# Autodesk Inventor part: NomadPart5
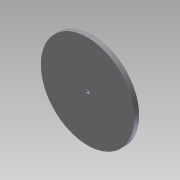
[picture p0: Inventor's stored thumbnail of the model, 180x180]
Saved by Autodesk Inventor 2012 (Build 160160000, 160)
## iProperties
Created: 2012-10
Part Number: NomadPart5
Material: Default
Document SubType Name: Modeling
Designer: TechShop Member
Density: 1 g/cm^3
Author: TechShop Member
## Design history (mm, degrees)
sketch "Sketch1"
  geometry: C1 r 61.139 at (0, 0); 1 further point
  constraints: 1 centre point, 1 coincident
  dimensions: "d0" = 122.27814 diameter of C1
extrude "Extrusion1" new body sketch "Sketch1" distance "d1" = 6.35; taper "d2" = 0 deg
sketch "Sketch2"
  geometry: C1 r 61.139 at (0, 0) reference; 1 further point
  constraints: 1 coincident
hole "Hole1" sketch "Sketch2" at (0, 0) diameter "d3" = 5.207; stored, may be unused: countersink angle "d7" = 82 deg, drill point angle "d9" = 118 deg; dims "d4" = 19.05, "d5" = 9.525, "d6" = 6.35, "d8" = 25.4
body "Solid1"
